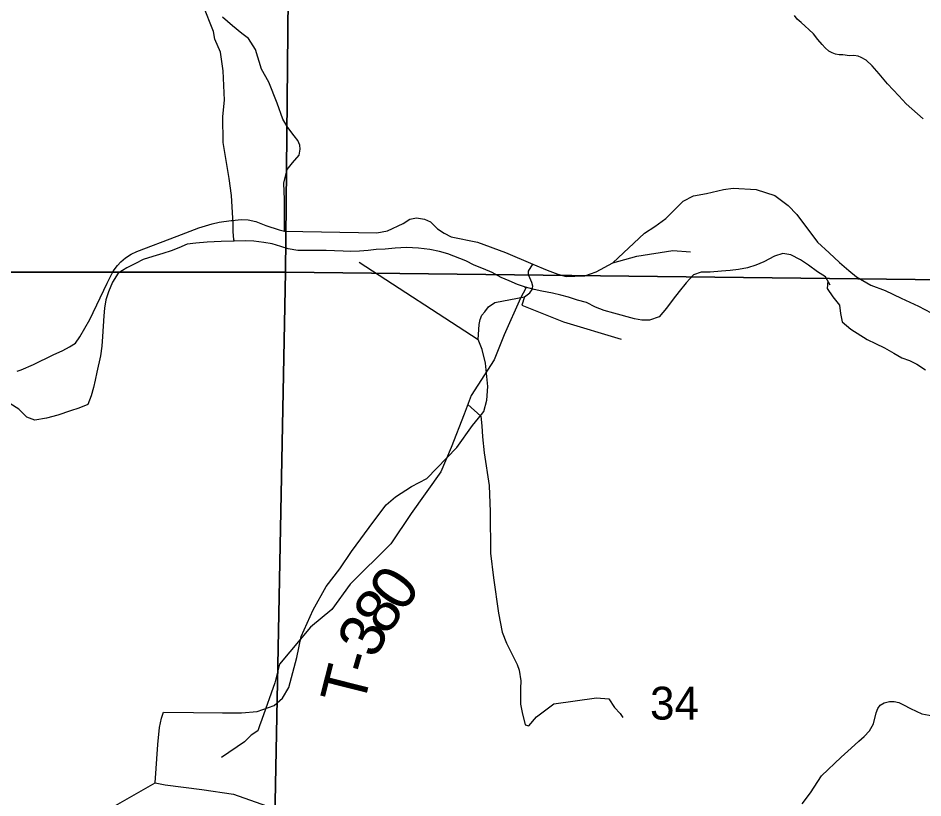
# Model space of a CAD drawing. Extents: x 2.1 to 8.9, y 14.1 to 20.9.
# Drawn here: x 6.096 to 7.249, y 16.441 to 17.436 of the extents above; entities that cross this region are included whole.
import ezdxf

# ---------------------------------------------------------------- set-up
doc = ezdxf.new("R2010")
doc.units = 0
for name, color, linetype in [('GM_X_City_Street', 7, 'Continuous'), ('GM_X_County_Road_Text', 7, 'Continuous'), ('GM_X_Interchange_Ramps', 7, 'Continuous'), ('GM_X_Minor_River_Text', 7, 'Continuous'), ('GM_X_State_Shield', 7, 'Continuous'), ('TX_P_Misc', 7, 'Continuous')]:
    doc.layers.add(name, color=color, linetype=linetype)

msp = doc.modelspace()

# ---------------------------------------------------------------- linework, layer by layer
at = {"layer": 'GM_X_City_Street'}
for p, q in [((6.3691, 17.4255), (6.3563, 17.4369)), ((7.0887, 17.4343), (7.0854, 17.4388)), ((7.0937, 17.4298), (7.0887, 17.4343)), ((6.3809, 17.416), (6.3691, 17.4255)), ((7.099, 17.4253), (7.0937, 17.4298)), ((7.1038, 17.421), (7.099, 17.4253)), ((6.3898, 17.4096), (6.3809, 17.416)), ((7.1094, 17.4156), (7.1038, 17.421)), ((7.1151, 17.4081), (7.1094, 17.4156)), ((6.3983, 17.3957), (6.3898, 17.4096)), ((7.1205, 17.402), (7.1151, 17.4081)), ((7.1245, 17.3977), (7.1205, 17.402)), ((6.4062, 17.3704), (6.3983, 17.3957)), ((7.1292, 17.3932), (7.1245, 17.3977)), ((7.1333, 17.3912), (7.1292, 17.3932)), ((7.1376, 17.3897), (7.1333, 17.3912)), ((7.1421, 17.3887), (7.1376, 17.3897)), ((7.147, 17.3889), (7.1421, 17.3887)), ((7.1553, 17.3875), (7.147, 17.3889)), ((7.1608, 17.388), (7.1553, 17.3875)), ((7.1666, 17.3871), (7.1608, 17.388)), ((7.1704, 17.3854), (7.1666, 17.3871)), ((7.1767, 17.3818), (7.1704, 17.3854)), ((7.1845, 17.3747), (7.1767, 17.3818)), ((6.4155, 17.3539), (6.4062, 17.3704)), ((7.1934, 17.3645), (7.1845, 17.3747)), ((7.2039, 17.3518), (7.1934, 17.3645)), ((6.4262, 17.3271), (6.4155, 17.3539)), ((7.2181, 17.3364), (7.2039, 17.3518)), ((7.2275, 17.3264), (7.2181, 17.3364)), ((6.4332, 17.3065), (6.4262, 17.3271)), ((7.2495, 17.3073), (7.2275, 17.3264)), ((6.4398, 17.2959), (6.4332, 17.3065)), ((6.4476, 17.2856), (6.4398, 17.2959)), ((6.4525, 17.2794), (6.4476, 17.2856)), ((6.4552, 17.2737), (6.4525, 17.2794)), ((6.4555, 17.2685), (6.4552, 17.2737)), ((6.4458, 17.2511), (6.454, 17.2606)), ((6.454, 17.2606), (6.4555, 17.2685)), ((6.4388, 17.2425), (6.4458, 17.2511)), ((6.4347, 17.2251), (6.4388, 17.2425)), ((6.4356, 17.2043), (6.4347, 17.2251)), ((6.4353, 17.164), (6.4356, 17.2043)), ((6.8843, 17.1322), (6.9302, 17.1391)), ((6.9302, 17.1391), (6.953, 17.1375)), ((6.5306, 17.1245), (6.6822, 17.0257)), ((6.8539, 17.1236), (6.8843, 17.1322)), ((6.7463, 17.1083), (6.7465, 17.113)), ((6.7465, 17.113), (6.7518, 17.1217)), ((6.7481, 17.1042), (6.7463, 17.1083)), ((6.7505, 17.0983), (6.7481, 17.1042)), ((6.7479, 17.0851), (6.751, 17.0893)), ((6.7519, 17.0937), (6.7505, 17.0983)), ((6.751, 17.0893), (6.7519, 17.0937)), ((6.7035, 17.0729), (6.7413, 17.0803)), ((6.7413, 17.0803), (6.738, 17.0697)), ((6.7413, 17.0803), (6.7479, 17.0851)), ((6.6908, 17.0608), (6.6954, 17.0674)), ((6.6954, 17.0674), (6.7035, 17.0729)), ((6.738, 17.0697), (6.791, 17.0482)), ((6.6846, 17.0511), (6.6871, 17.0569)), ((6.6871, 17.0569), (6.6908, 17.0608)), ((6.6822, 17.0257), (6.6837, 17.0449)), ((6.6837, 17.0449), (6.6846, 17.0511)), ((6.791, 17.0482), (6.8644, 17.026)), ((6.6873, 17.0131), (6.6822, 17.0257)), ((6.6917, 16.9955), (6.6873, 17.0131)), ((6.6947, 16.966), (6.6917, 16.9955)), ((6.6932, 16.9482), (6.6947, 16.966)), ((6.6896, 16.934), (6.6932, 16.9482)), ((6.6751, 16.9162), (6.6865, 16.9301)), ((6.6865, 16.9301), (6.6896, 16.934)), ((6.6551, 16.8881), (6.6751, 16.9162)), ((6.6169, 16.8485), (6.6551, 16.8881)), ((6.5975, 16.8385), (6.6169, 16.8485)), ((6.577, 16.825), (6.5975, 16.8385)), ((6.5652, 16.815), (6.577, 16.825)), ((6.5494, 16.7942), (6.5652, 16.815)), ((6.5209, 16.7553), (6.5494, 16.7942)), ((6.5059, 16.7331), (6.5209, 16.7553)), ((6.4886, 16.7106), (6.5059, 16.7331)), ((6.4721, 16.6812), (6.4886, 16.7106)), ((6.4568, 16.6472), (6.4721, 16.6812)), ((6.451, 16.6201), (6.4568, 16.6472)), ((6.441, 16.582), (6.451, 16.6201)), ((6.4328, 16.5682), (6.441, 16.582)), ((6.4008, 16.5512), (6.4225, 16.5591)), ((6.4225, 16.5591), (6.4328, 16.5682)), ((7.1915, 16.5552), (7.1947, 16.5595)), ((7.1947, 16.5595), (7.1998, 16.5625)), ((7.1998, 16.5625), (7.2066, 16.5641)), ((7.2066, 16.5641), (7.2123, 16.5641)), ((7.2123, 16.5641), (7.2181, 16.5629)), ((7.2181, 16.5629), (7.2243, 16.56)), ((7.2243, 16.56), (7.233, 16.5553)), ((6.2786, 16.5431), (6.2813, 16.5506)), ((6.2813, 16.5506), (6.3196, 16.5502)), ((6.3196, 16.5502), (6.3563, 16.5495)), ((6.3563, 16.5495), (6.3805, 16.5497)), ((6.3805, 16.5497), (6.4008, 16.5512)), ((7.1861, 16.5358), (7.1894, 16.5495)), ((7.1894, 16.5495), (7.1915, 16.5552)), ((7.233, 16.5553), (7.2476, 16.5485)), ((7.2476, 16.5485), (7.2617, 16.546)), ((6.2763, 16.5311), (6.2786, 16.5431)), ((7.181, 16.5268), (7.1861, 16.5358)), ((6.2741, 16.5095), (6.2763, 16.5311)), ((7.174, 16.5193), (7.181, 16.5268)), ((7.1577, 16.5047), (7.1673, 16.5137)), ((7.1673, 16.5137), (7.174, 16.5193)), ((6.2708, 16.4605), (6.2741, 16.5095)), ((7.1448, 16.4932), (7.1577, 16.5047)), ((7.1199, 16.4693), (7.1448, 16.4932)), ((7.1058, 16.4475), (7.1199, 16.4693)), ((6.097, 16.3616), (6.2708, 16.4605)), ((6.2708, 16.4605), (6.2836, 16.4578)), ((6.2836, 16.4578), (6.3302, 16.4518)), ((6.3302, 16.4518), (6.3703, 16.4458)), ((6.3703, 16.4458), (6.4124, 16.4309)), ((7.0953, 16.4338), (7.1058, 16.4475))]:
    msp.add_line(p, q, dxfattribs=at)
at = {"layer": 'GM_X_Interchange_Ramps'}
for p, q in [((6.4465, 18.0895), (6.4366, 17.1114)), ((6.4366, 17.1114), (6.4465, 18.0895)), ((6.4366, 17.1114), (5.492, 17.1117)), ((5.492, 17.1117), (6.4366, 17.1114)), ((6.4161, 16.0534), (6.4366, 17.1114)), ((6.4366, 17.1114), (6.4161, 16.0534)), ((7.441, 17.0998), (6.4366, 17.1114)), ((6.4366, 17.1114), (7.441, 17.0998))]:
    msp.add_line(p, q, dxfattribs=at)
at = {"layer": 'GM_X_State_Shield'}
for p, q in [((6.9733, 17.2121), (6.9949, 17.2169)), ((6.9949, 17.2169), (7.0071, 17.2188)), ((7.0071, 17.2188), (7.0364, 17.2172)), ((7.0364, 17.2172), (7.0602, 17.2092)), ((6.9435, 17.2023), (6.9567, 17.2088)), ((6.9567, 17.2088), (6.9733, 17.2121)), ((7.0602, 17.2092), (7.0772, 17.1966)), ((6.9212, 17.1802), (6.9435, 17.2023)), ((7.0772, 17.1966), (7.0882, 17.1851)), ((6.5953, 17.1792), (6.6035, 17.1807)), ((6.6035, 17.1807), (6.6138, 17.1792)), ((6.9072, 17.17), (6.9212, 17.1802)), ((7.0882, 17.1851), (7.1148, 17.15)), ((6.2988, 17.1577), (6.3261, 17.1683)), ((6.3261, 17.1683), (6.3431, 17.1733)), ((6.3431, 17.1733), (6.3524, 17.1753)), ((6.3524, 17.1753), (6.3677, 17.1775)), ((6.3677, 17.1775), (6.3687, 17.1776)), ((6.3687, 17.1776), (6.3803, 17.1787)), ((6.3803, 17.1787), (6.389, 17.1782)), ((6.389, 17.1782), (6.399, 17.176)), ((6.399, 17.176), (6.4116, 17.171)), ((6.4116, 17.171), (6.4285, 17.1654)), ((6.5666, 17.1645), (6.5868, 17.1735)), ((6.5868, 17.1735), (6.5953, 17.1792)), ((6.6138, 17.1792), (6.6215, 17.1757)), ((6.6215, 17.1757), (6.6305, 17.167)), ((6.8942, 17.1612), (6.9072, 17.17)), ((6.2472, 17.1381), (6.2988, 17.1577)), ((6.4285, 17.1654), (6.4353, 17.164)), ((6.4353, 17.164), (6.5533, 17.1619)), ((6.5533, 17.1619), (6.5666, 17.1645)), ((6.6305, 17.167), (6.639, 17.1613)), ((6.639, 17.1613), (6.648, 17.1568)), ((6.648, 17.1568), (6.6812, 17.15)), ((6.8539, 17.1236), (6.8942, 17.1612)), ((6.6812, 17.15), (6.7171, 17.1368)), ((7.1148, 17.15), (7.1297, 17.1362)), ((6.233, 17.1299), (6.2402, 17.1346)), ((6.2402, 17.1346), (6.2472, 17.1381)), ((6.7171, 17.1368), (6.7518, 17.1217)), ((7.1297, 17.1362), (7.1428, 17.1241)), ((6.2228, 17.1202), (6.2268, 17.1246)), ((6.2268, 17.1246), (6.233, 17.1299)), ((6.8325, 17.112), (6.8539, 17.1236)), ((7.1428, 17.1241), (7.1547, 17.1138)), ((6.2097, 17.0976), (6.2159, 17.1105)), ((6.2159, 17.1105), (6.2186, 17.1145)), ((6.2186, 17.1145), (6.2228, 17.1202)), ((6.7518, 17.1217), (6.7701, 17.1142)), ((6.7701, 17.1142), (6.7836, 17.1092)), ((6.8183, 17.1071), (6.8325, 17.112)), ((7.1547, 17.1138), (7.1644, 17.1055)), ((6.7836, 17.1092), (6.7946, 17.106)), ((6.7946, 17.106), (6.8054, 17.1065)), ((6.8054, 17.1065), (6.8183, 17.1071)), ((7.1644, 17.1055), (7.1827, 17.0952)), ((6.1872, 17.0512), (6.2097, 17.0976)), ((7.1827, 17.0952), (7.201, 17.0881)), ((7.201, 17.0881), (7.2211, 17.0784)), ((7.2211, 17.0784), (7.2434, 17.0683)), ((7.2434, 17.0683), (7.2676, 17.0553)), ((6.1745, 17.0291), (6.1872, 17.0512)), ((6.1614, 17.0162), (6.169, 17.0212)), ((6.169, 17.0212), (6.1745, 17.0291)), ((6.1407, 17.0061), (6.1528, 17.0116)), ((6.1528, 17.0116), (6.1614, 17.0162)), ((6.1155, 16.994), (6.1407, 17.0061)), ((6.0949, 16.9852), (6.1, 16.987)), ((6.1, 16.987), (6.1155, 16.994))]:
    msp.add_line(p, q, dxfattribs=at)
at = {"layer": 'TX_P_Misc'}
for p, q in [((6.345, 17.4185), (6.332, 17.4518)), ((6.3467, 17.4086), (6.345, 17.4185)), ((6.3538, 17.3923), (6.3467, 17.4086)), ((6.3572, 17.3684), (6.3538, 17.3923)), ((6.359, 17.3307), (6.3572, 17.3684)), ((6.357, 17.3101), (6.359, 17.3307)), ((6.3572, 17.277), (6.357, 17.3101)), ((6.3648, 17.2311), (6.3572, 17.277)), ((6.3678, 17.2094), (6.3648, 17.2311)), ((6.3699, 17.1733), (6.3678, 17.2094)), ((6.3701, 17.1634), (6.3699, 17.1733)), ((6.3707, 17.1527), (6.3701, 17.1634)), ((6.3115, 17.1472), (6.3007, 17.1427)), ((6.3225, 17.1487), (6.3115, 17.1472)), ((6.3369, 17.1499), (6.3225, 17.1487)), ((6.3548, 17.1509), (6.3369, 17.1499)), ((6.3715, 17.151), (6.3548, 17.1509)), ((6.3722, 17.151), (6.3707, 17.1527)), ((6.3859, 17.1515), (6.3715, 17.151)), ((6.3966, 17.151), (6.3859, 17.1515)), ((6.4092, 17.1495), (6.3966, 17.151)), ((6.4199, 17.1476), (6.4092, 17.1495)), ((6.4306, 17.1445), (6.4199, 17.1476)), ((6.2804, 17.1352), (6.2675, 17.1314)), ((6.2909, 17.1386), (6.2804, 17.1352)), ((6.3007, 17.1427), (6.2909, 17.1386)), ((6.4402, 17.1414), (6.4306, 17.1445)), ((6.4525, 17.1391), (6.4402, 17.1414)), ((6.4642, 17.1394), (6.4525, 17.1391)), ((6.4764, 17.1391), (6.4642, 17.1394)), ((6.4886, 17.1394), (6.4764, 17.1391)), ((6.4992, 17.1386), (6.4886, 17.1394)), ((6.5103, 17.1382), (6.4992, 17.1386)), ((6.5198, 17.1381), (6.5103, 17.1382)), ((6.5312, 17.1385), (6.5198, 17.1381)), ((6.5422, 17.1392), (6.5312, 17.1385)), ((6.5524, 17.1403), (6.5422, 17.1392)), ((6.5638, 17.141), (6.5524, 17.1403)), ((6.5763, 17.1422), (6.5638, 17.141)), ((6.5911, 17.143), (6.5763, 17.1422)), ((6.6063, 17.1424), (6.5911, 17.143)), ((6.6205, 17.1405), (6.6063, 17.1424)), ((6.6331, 17.1379), (6.6205, 17.1405)), ((6.6434, 17.1348), (6.6331, 17.1379)), ((6.6665, 17.126), (6.6434, 17.1348)), ((7.0704, 17.1352), (7.0598, 17.1318)), ((7.0807, 17.1336), (7.0704, 17.1352)), ((7.093, 17.1275), (7.0807, 17.1336)), ((6.2454, 17.1227), (6.2345, 17.117)), ((6.2555, 17.1276), (6.2454, 17.1227)), ((6.2675, 17.1314), (6.2555, 17.1276)), ((6.677, 17.1206), (6.6665, 17.126)), ((7.0464, 17.1249), (7.0362, 17.1204)), ((7.0598, 17.1318), (7.0464, 17.1249)), ((7.1031, 17.1206), (7.093, 17.1275)), ((6.2345, 17.117), (6.2233, 17.1102)), ((6.6889, 17.116), (6.677, 17.1206)), ((6.7001, 17.111), (6.6889, 17.116)), ((6.7116, 17.1049), (6.7001, 17.111)), ((6.9665, 17.1114), (6.9568, 17.108)), ((6.9779, 17.1117), (6.9665, 17.1114)), ((6.9924, 17.113), (6.9779, 17.1117)), ((7.0034, 17.1137), (6.9924, 17.113)), ((7.014, 17.1148), (7.0034, 17.1137)), ((7.0253, 17.117), (7.014, 17.1148)), ((7.0362, 17.1204), (7.0253, 17.117)), ((7.1148, 17.1122), (7.1031, 17.1206)), ((7.1249, 17.1057), (7.1148, 17.1122)), ((6.2161, 17.0989), (6.2111, 17.0866)), ((6.2233, 17.1102), (6.2161, 17.0989)), ((6.7217, 17.1007), (6.7116, 17.1049)), ((6.7324, 17.096), (6.7217, 17.1007)), ((6.9568, 17.108), (6.9472, 17.0978)), ((7.131, 17.0952), (7.1249, 17.1057)), ((7.1279, 17.1006), (7.1268, 17.0907)), ((6.7424, 17.0925), (6.7324, 17.096)), ((6.7429, 17.0911), (6.7363, 17.0784)), ((6.7414, 17.0929), (6.7429, 17.0911)), ((6.7536, 17.0895), (6.7424, 17.0925)), ((6.7635, 17.0875), (6.7536, 17.0895)), ((6.7769, 17.0849), (6.7635, 17.0875)), ((6.9472, 17.0978), (6.9384, 17.0869)), ((7.1268, 17.0907), (7.1342, 17.0802)), ((6.2076, 17.0762), (6.2061, 17.0658)), ((6.2111, 17.0866), (6.2076, 17.0762)), ((6.7363, 17.0784), (6.7152, 17.0316)), ((6.7876, 17.0821), (6.7769, 17.0849)), ((6.7972, 17.0798), (6.7876, 17.0821)), ((6.8087, 17.0759), (6.7972, 17.0798)), ((6.8202, 17.0729), (6.8087, 17.0759)), ((6.9307, 17.0771), (6.9223, 17.0658)), ((6.9384, 17.0869), (6.9307, 17.0771)), ((7.1342, 17.0802), (7.1429, 17.0694)), ((6.2061, 17.0658), (6.2052, 17.0559)), ((6.8318, 17.0671), (6.8202, 17.0729)), ((6.8429, 17.0629), (6.8318, 17.0671)), ((6.9223, 17.0658), (6.9131, 17.0548)), ((7.1429, 17.0694), (7.1439, 17.0587)), ((6.2052, 17.0559), (6.2045, 17.0429)), ((6.8552, 17.0591), (6.8429, 17.0629)), ((6.8813, 17.0519), (6.8552, 17.0591)), ((6.9131, 17.0548), (6.9007, 17.0503)), ((7.1439, 17.0587), (7.1461, 17.0481)), ((6.2045, 17.0429), (6.2037, 17.0296)), ((6.8908, 17.0503), (6.8813, 17.0519)), ((6.9007, 17.0503), (6.8908, 17.0503)), ((7.1461, 17.0481), (7.157, 17.0389)), ((6.7152, 17.0316), (6.7025, 16.9998)), ((7.157, 17.0389), (7.1779, 17.0257)), ((6.2037, 17.0296), (6.2026, 17.0173)), ((7.1779, 17.0257), (7.1886, 17.0207)), ((7.1886, 17.0207), (7.2002, 17.0149)), ((6.2026, 17.0173), (6.2011, 17.0047)), ((7.2002, 17.0149), (7.2118, 17.0083)), ((7.2118, 17.0083), (7.2222, 17.0022)), ((6.2011, 17.0047), (6.1964, 16.984)), ((6.7025, 16.9998), (6.6734, 16.9543)), ((7.2222, 17.0022), (7.2318, 16.999)), ((7.2318, 16.999), (7.2414, 16.9943)), ((6.1964, 16.984), (6.194, 16.974)), ((7.2414, 16.9943), (7.2522, 16.987)), ((6.194, 16.974), (6.192, 16.9644)), ((6.192, 16.9644), (6.1893, 16.9541)), ((6.1893, 16.9541), (6.1847, 16.9429)), ((6.6734, 16.9543), (6.6643, 16.9306)), ((6.0971, 16.9367), (6.0855, 16.944)), ((6.1734, 16.9383), (6.1629, 16.9346)), ((6.1847, 16.9429), (6.1734, 16.9383)), ((6.6691, 16.943), (6.6856, 16.9279)), ((6.1073, 16.9267), (6.0971, 16.9367)), ((6.1173, 16.9229), (6.1073, 16.9267)), ((6.1467, 16.9291), (6.132, 16.9256)), ((6.1629, 16.9346), (6.1467, 16.9291)), ((6.6643, 16.9306), (6.6477, 16.888)), ((6.6856, 16.9279), (6.6869, 16.9157)), ((6.132, 16.9256), (6.1173, 16.9229)), ((6.6869, 16.9157), (6.6879, 16.9017)), ((6.6879, 16.9017), (6.6901, 16.8811)), ((6.6477, 16.888), (6.6346, 16.857)), ((6.6901, 16.8811), (6.6961, 16.8397)), ((6.6346, 16.857), (6.5969, 16.8038)), ((6.6961, 16.8397), (6.6975, 16.8059)), ((6.5969, 16.8038), (6.5708, 16.7653)), ((6.6975, 16.8059), (6.698, 16.7533)), ((6.5708, 16.7653), (6.5191, 16.7138)), ((6.698, 16.7533), (6.7019, 16.7218)), ((6.7019, 16.7218), (6.7083, 16.6766)), ((6.5191, 16.7138), (6.4958, 16.6815)), ((6.4958, 16.6815), (6.4686, 16.6589)), ((6.7083, 16.6766), (6.7129, 16.6527)), ((6.4686, 16.6589), (6.429, 16.6118)), ((6.7129, 16.6527), (6.7184, 16.6387)), ((6.7184, 16.6387), (6.7321, 16.6115)), ((6.429, 16.6118), (6.423, 16.5878)), ((6.7321, 16.6115), (6.7345, 16.6043)), ((6.7345, 16.6043), (6.7367, 16.5903)), ((6.423, 16.5878), (6.4064, 16.5411)), ((6.7367, 16.5903), (6.7361, 16.5807)), ((6.7361, 16.5807), (6.7364, 16.5606)), ((6.7787, 16.5613), (6.833, 16.569)), ((6.833, 16.569), (6.8486, 16.5674)), ((6.7364, 16.5606), (6.7385, 16.55)), ((6.7564, 16.5445), (6.7787, 16.5613)), ((6.8486, 16.5674), (6.8559, 16.5565)), ((6.7385, 16.55), (6.7422, 16.5344)), ((6.8559, 16.5565), (6.8632, 16.549)), ((6.8632, 16.549), (6.8664, 16.5437)), ((6.4064, 16.5411), (6.4035, 16.533)), ((6.7422, 16.5344), (6.7467, 16.5333)), ((6.7467, 16.5333), (6.7564, 16.5445)), ((6.4013, 16.5269), (6.3931, 16.5214)), ((6.4035, 16.533), (6.4013, 16.5269)), ((6.3846, 16.5125), (6.3551, 16.4926)), ((6.3931, 16.5214), (6.3846, 16.5125))]:
    msp.add_line(p, q, dxfattribs=at)

# ---------------------------------------------------------------- texts
at = {"layer": 'GM_X_County_Road_Text'}
msp.add_text('34', height=0.04186, rotation=0, dxfattribs=at).set_placement((6.9013, 16.5411))
at = {"layer": 'GM_X_Minor_River_Text'}
for s, rotation, p in [('0', 55.3505, (6.5863, 16.6757)), ('8', 54.3177, (6.5652, 16.6464)), ('3', 64.7174, (6.5516, 16.6171)), ('-', 73.8637, (6.546, 16.5969)), ('T', 75.811, (6.5357, 16.5562))]:
    msp.add_text(s, height=0.0568, rotation=rotation, dxfattribs=at).set_placement(p)

doc.saveas('drawing.dxf')
